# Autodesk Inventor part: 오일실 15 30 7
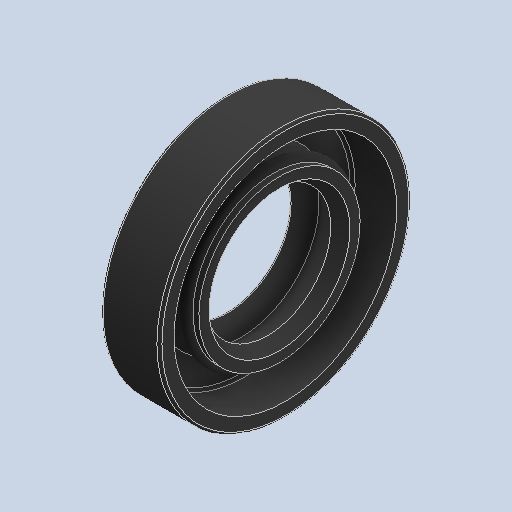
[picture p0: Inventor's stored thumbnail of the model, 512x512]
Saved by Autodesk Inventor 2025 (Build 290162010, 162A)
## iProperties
Created: 2024-07
Part Number: 오일실 15 30 7
Material: 고무
Description: 오일-실
Document SubType Name: Modeling
Designer: Admin
Density: 0.93 g/cm^3
Appearance: 기본값
Author: jhkim
Sending System: Autodesk Inventor 2025
Preprocessor: ST-DEVELOPER v20
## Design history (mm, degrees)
feature "Solid1"
node "솔리드1"
